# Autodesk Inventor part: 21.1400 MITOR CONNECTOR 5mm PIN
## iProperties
Created: 2007-05
Part Number: 21.1400 MITOR CONNECTOR 5mm PIN
Material: Alloy Steel
Document SubType Name: Modeling
Designer: Andy Moles
Density: 7.85 g/cm^3
Mass: 1.26949 g
Surface Area: 1.82355 cm^2
Volume: 0.161718 cm^3
Author: Andy Moles
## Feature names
1. Revolution1
